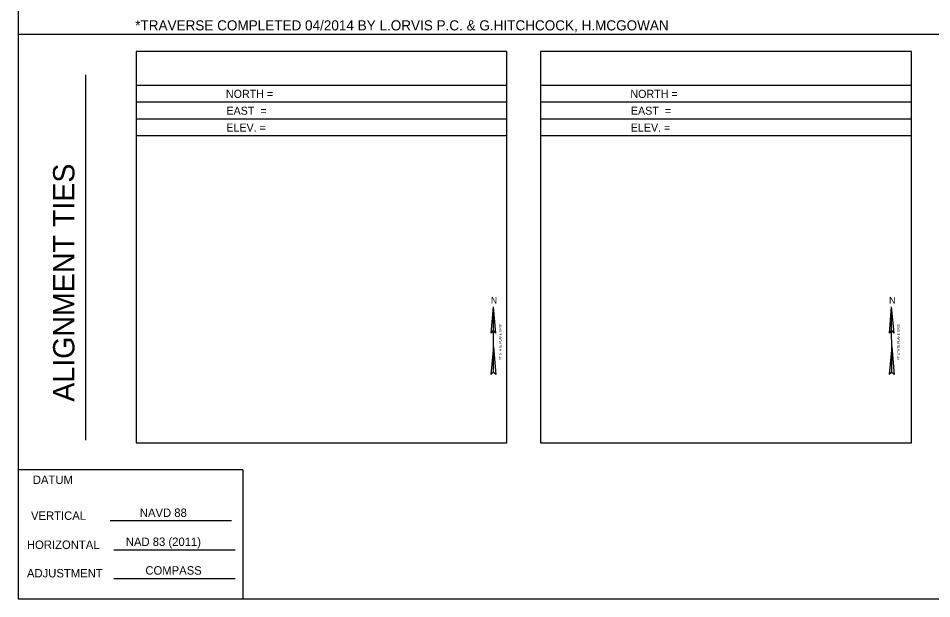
# Model space of a CAD drawing. Extents: x 1454446 to 1455086, y 375501 to 375921.
# Drawn here: x 1454446.4 to 1454717.4, y 375500.6 to 375672.7 of the extents above; entities that cross this region are included whole.
import ezdxf

# ---------------------------------------------------------------- set-up
doc = ezdxf.new("R2010")
doc.units = 0
for name, color, linetype in [('Default', 7, 'Continuous'), ('NBL1', 7, 'Continuous'), ('NBL2', 7, 'Continuous'), ('NNA_P', 7, 'Continuous')]:
    doc.layers.add(name, color=color, linetype=linetype)

msp = doc.modelspace()

# ---------------------------------------------------------------- linework, layer by layer
at = {"layer": 'NBL1'}
msp.add_lwpolyline([(1454446.38, 375500.6), (1455086.38, 375500.6), (1455086.38, 375920.6), (1454446.38, 375920.6)], close=True, dxfattribs=at)
at = {"layer": 'NBL2'}
for p, q in [((1454446.38, 375667.93), (1455086.38, 375667.93)), ((1454466.38, 375547.6), (1454466.38, 375655.93)), ((1454591.37, 375652.77), (1454481.37, 375652.77)), ((1454711.37, 375652.77), (1454601.37, 375652.77)), ((1454591.37, 375647.77), (1454481.37, 375647.77)), ((1454711.37, 375647.77), (1454601.37, 375647.77)), ((1454591.37, 375642.77), (1454481.37, 375642.77)), ((1454711.37, 375642.77), (1454601.37, 375642.77)), ((1454591.37, 375637.77), (1454481.37, 375637.77)), ((1454711.37, 375637.77), (1454601.37, 375637.77)), ((1454513.04, 375538.85), (1454446.38, 375538.85)), ((1454513.04, 375538.85), (1454513.04, 375500.6)), ((1454513.04, 375538.85), (1454513.04, 375500.6)), ((1454473.62, 375523.83), (1454509.62, 375523.8)), ((1454474.73, 375515.05), (1454510.73, 375515.05)), ((1454474.73, 375506.62), (1454510.73, 375506.59))]:
    msp.add_line(p, q, dxfattribs=at)
for points in [[(1454481.37, 375546.77), (1454591.37, 375546.77), (1454591.37, 375662.77), (1454481.37, 375662.77)], [(1454601.37, 375546.77), (1454711.37, 375546.77), (1454711.37, 375662.77), (1454601.37, 375662.77)]]:
    msp.add_lwpolyline(points, close=True, dxfattribs=at)
at = {"layer": 'NNA_P'}
for p, q in [((1454586.64, 375579.31), (1454587.33, 375587.1)), ((1454587.33, 375567.73), (1454587.33, 375587.1)), ((1454588.02, 375579.31), (1454587.33, 375587.1)), ((1454704.82, 375579.31), (1454705.51, 375587.1)), ((1454705.52, 375567.73), (1454705.51, 375587.1)), ((1454706.21, 375579.31), (1454705.51, 375587.1)), ((1454586.64, 375579.31), (1454587.33, 375580.08)), ((1454588.03, 375579.31), (1454587.33, 375580.08)), ((1454704.82, 375579.31), (1454705.52, 375580.08)), ((1454706.21, 375579.31), (1454705.52, 375580.08)), ((1454587.34, 375575.25), (1454586.61, 375567.09)), ((1454587.33, 375575.25), (1454588.05, 375567.09)), ((1454705.52, 375575.25), (1454704.8, 375567.09)), ((1454705.52, 375575.25), (1454706.24, 375567.09)), ((1454587.33, 375567.73), (1454586.61, 375567.09)), ((1454587.33, 375567.73), (1454588.05, 375567.09)), ((1454705.52, 375567.73), (1454704.8, 375567.09)), ((1454705.52, 375567.73), (1454706.24, 375567.09))]:
    msp.add_line(p, q, dxfattribs=at)

# ---------------------------------------------------------------- texts
at = {"layer": 'Default'}
msp.add_text('*TRAVERSE COMPLETED 04/2014 BY L.ORVIS P.C. & G.HITCHCOCK, H.MCGOWAN', height=3, dxfattribs=at).set_placement((1454481.08, 375669.07))
at = {"layer": 'NBL2'}
for s, height, p in [('NORTH =             ', 2.375, (1454507.99, 375649.08)), ('NORTH =             ', 2.375, (1454627.99, 375649.08)), ('EAST  =             ', 2.375, (1454508.14, 375644.08)), ('EAST  =             ', 2.375, (1454628.14, 375644.08)), ('ELEV. =             ', 2.375, (1454508.1, 375639.08)), ('ELEV. =             ', 2.375, (1454628.1, 375639.08)), ('DATUM', 2.5, (1454450.69, 375534.61)), ('  NAVD 88 ', 2.5, (1454480.59, 375524.84)), ('NAD 83 (2011)  ', 2.5, (1454478.29, 375516.23)), ('HORIZONTAL', 2.5, (1454448.95, 375515.35)), ('ADJUSTMENT', 2.5, (1454448.95, 375506.92)), ('   COMPASS', 2.5, (1454481.3, 375507.74))]:
    msp.add_text(s, height=height, dxfattribs=at).set_placement(p)
for s, height, rotation, p in [('ALIGNMENT TIES', 6.3332, 90, (1454463.04, 375559)), ('VERTICAL', 2.5, 0.1439, (1454450.15, 375523.95))]:
    msp.add_text(s, height=height, rotation=rotation, dxfattribs=at).set_placement(p)
at = {"layer": 'NNA_P'}
for p in [(1454586.57, 375588.11), (1454704.75, 375588.11)]:
    msp.add_text('N', height=1.97, dxfattribs=at).set_placement(p)
for p in [(1454589.68, 375571.29), (1454707.87, 375571.29)]:
    msp.add_text('VT STATE PLANE GRID', height=0.7, rotation=90.0204, dxfattribs=at).set_placement(p)

doc.saveas('drawing.dxf')
